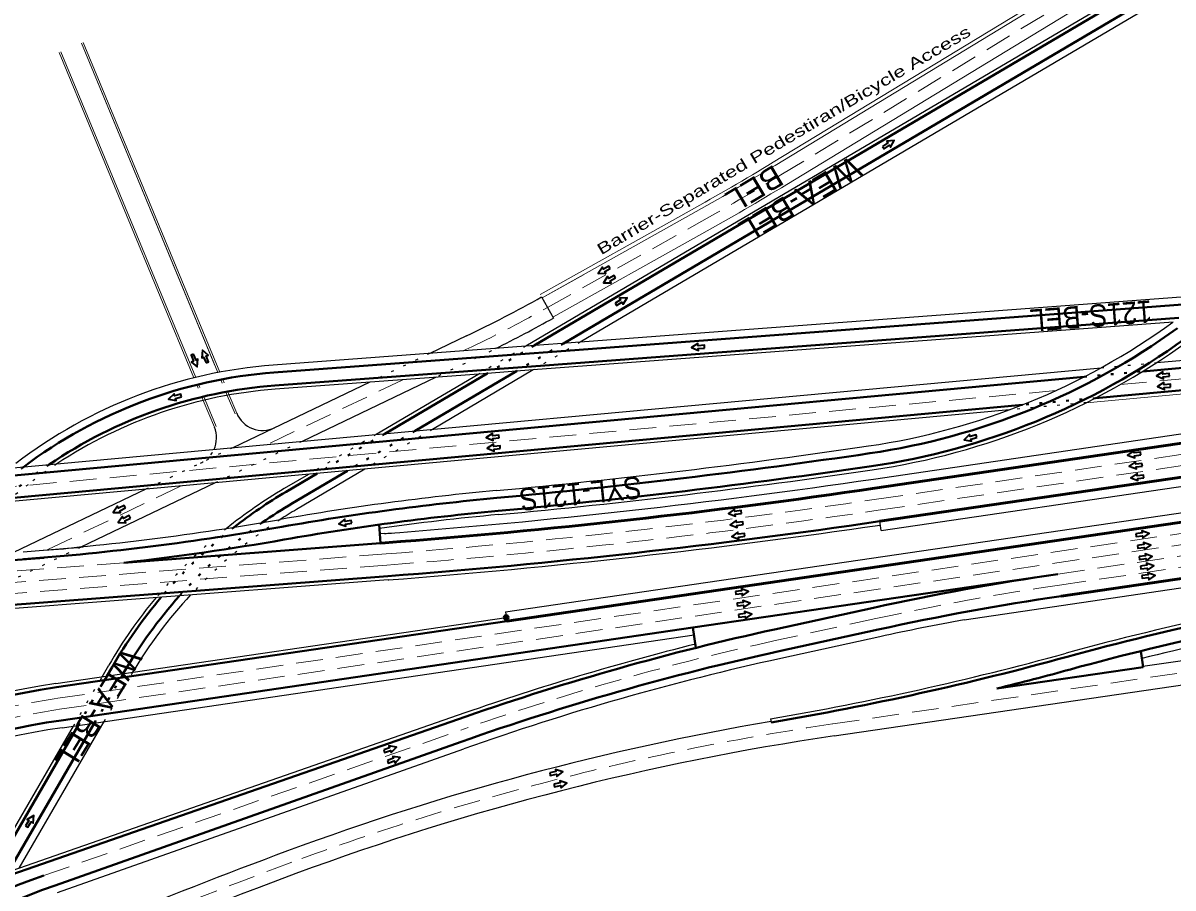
# Model space of a CAD drawing. Extents: x 2329387 to 2347382, y 6951580 to 6987999.
# Drawn here: x 2332942 to 2334179, y 6964414 to 6965345 of the extents above; entities that cross this region are included whole.
import ezdxf

# ---------------------------------------------------------------- set-up
doc = ezdxf.new("R2010")
doc.units = 0
doc.header["$LTSCALE"] = 9.6
doc.header["$PDMODE"] = 32
doc.header["$PDSIZE"] = 4.8
doc.linetypes.add('DOTTED', pattern=[1.5, 0.3, -1.2])
doc.linetypes.add('MEDIUM_DASHED', pattern=[4.5, 3, -1.5])
for name, color, linetype, lineweight in [('26', 7, 'Continuous', 53), ('27', 7, 'Continuous', 40), ('28', 7, 'Continuous', 25), ('3', 7, 'Continuous', 13), ('41', 7, 'Continuous', 35), ('50', 7, 'MEDIUM_DASHED', 13)]:
    doc.layers.add(name, color=color, linetype=linetype, lineweight=lineweight)
doc.layers.add('40', color=7, linetype='Continuous')

msp = doc.modelspace()

# ---------------------------------------------------------------- linework, layer by layer
at = {"layer": '26', "lineweight": 25}
for p, q in [((2333856.94, 6964854.018), (2334717.176, 6964980.367)), ((2333865.078, 6964798.612), (2334838.157, 6964941.536)), ((2333460.788, 6964710.931), (2334837.888, 6964913.196)), ((2333954.558, 6964702.596), (2334837.12, 6964832.225)), ((2333865.078, 6964798.612), (2333863.625, 6964808.506)), ((2333330.761, 6964795.33), (2333325.743, 6964794.947)), ((2333460.788, 6964710.931), (2333462.241, 6964701.037))]:
    msp.add_line(p, q, dxfattribs=at)
at = {"layer": '26'}
for p, q in [((2333858.393, 6964844.124), (2334718.629, 6964970.474)), ((2333863.625, 6964808.506), (2334838.253, 6964951.657)), ((2333462.241, 6964701.037), (2334837.792, 6964903.075)), ((2334058.85, 6964728.022), (2334837.216, 6964842.346)), ((2333331.527, 6964785.36), (2333326.499, 6964784.975))]:
    msp.add_line(p, q, dxfattribs=at)
at = {"layer": '26', "lineweight": 25}
for start, end in [(274.37265, 278.35573), (274.37261, 274.42831)]:
    msp.add_arc((2332749.984, 6972390.598), 7617.44, start, end, dxfattribs=at)
at = {"layer": '26'}
msp.add_arc((2332749.984, 6972390.598), 7627.44, 274.37267, 278.35573, dxfattribs=at)
at = {"layer": '27', "lineweight": 25}
for p, q in [((2334135.256, 6965381.515), (2333482.819, 6964996.963)), ((2334148.458, 6965359.116), (2333541.47, 6965001.352)), ((2334223.01, 6965052.354), (2333541.47, 6965001.352)), ((2334161.708, 6964979.364), (2334839.107, 6965041.79)), ((2334179.397, 6965023.018), (2333490.801, 6964971.488)), ((2333541.47, 6965001.352), (2333482.819, 6964996.963)), ((2333482.819, 6964996.963), (2333211.077, 6964976.628)), ((2332915.444, 6964864.514), (2334101.913, 6964973.853)), ((2333432.151, 6964967.099), (2333213.018, 6964950.701)), ((2333432.151, 6964967.099), (2333321.608, 6964901.944)), ((2333490.801, 6964971.488), (2333382.302, 6964907.537)), ((2333490.801, 6964971.488), (2333432.151, 6964967.099)), ((2334003.397, 6964928.622), (2332585.403, 6964797.946)), ((2333309.597, 6964864.685), (2333235.951, 6964821.277)), ((2333248.903, 6964859.091), (2333222.748, 6964843.675)), ((2333334.547, 6964745.474), (2333044.587, 6964723.303)), ((2333044.587, 6964723.303), (2332756.491, 6964701.275)), ((2332977.04, 6964633.814), (2333461.66, 6964704.994)), ((2332984.013, 6964586.324), (2333663.872, 6964686.18)), ((2333863.859, 6964684.262), (2333757.104, 6964660.877)), ((2333026.817, 6964641.126), (2333034.057, 6964653.615)), ((2333417.24, 6964602.202), (2332888.696, 6964418.182)), ((2332937.472, 6964435.164), (2333028.925, 6964592.92)), ((2333746.233, 6964595.957), (2333746.903, 6964592.013)), ((2332910.5, 6964440.478), (2332996.075, 6964588.095)), ((2332978.864, 6964409.03), (2333415.952, 6964563.598))]:
    msp.add_line(p, q, dxfattribs=at)
at = {"layer": '27'}
for p, q in [((2334137.287, 6965378.069), (2333491.842, 6964997.639)), ((2334144.396, 6965366.008), (2333523.423, 6965000.002)), ((2334208.79, 6965043.268), (2333525.879, 6964992.163)), ((2334185.648, 6965027.497), (2333498.596, 6964976.082)), ((2334146.832, 6964969.959), (2334839.031, 6965033.749)), ((2334838.802, 6965009.626), (2334095.849, 6964941.159)), ((2333525.879, 6964992.163), (2333467.229, 6964987.774)), ((2333467.229, 6964987.774), (2333211.674, 6964968.65)), ((2333498.596, 6964976.082), (2333439.946, 6964971.693)), ((2332916.178, 6964856.548), (2334083.684, 6964964.14)), ((2333439.946, 6964971.693), (2333212.719, 6964954.689)), ((2333441.174, 6964967.774), (2333330.945, 6964902.805)), ((2333472.755, 6964970.138), (2333363.627, 6964905.816)), ((2334017.13, 6964933.905), (2332585.036, 6964801.929)), ((2333258.241, 6964859.952), (2333224.78, 6964840.23)), ((2333290.922, 6964862.964), (2333231.888, 6964828.169)), ((2333324.987, 6964804.918), (2333326.499, 6964784.977)), ((2333326.499, 6964784.975), (2333050.228, 6964763.851)), ((2332964.682, 6964769.345), (2332752.526, 6964753.123)), ((2333334.226, 6964749.461), (2332756.186, 6964705.263)), ((2333662.709, 6964694.095), (2334055.362, 6964751.767)), ((2333857.012, 6964715.521), (2333750.267, 6964692.138)), ((2332977.621, 6964629.857), (2333462.241, 6964701.037)), ((2332982.86, 6964594.24), (2333662.709, 6964694.095)), ((2333665.906, 6964672.328), (2333662.709, 6964694.095)), ((2333862.147, 6964692.077), (2333755.392, 6964668.692)), ((2334144.509, 6964668.841), (2334147.052, 6964651.527)), ((2333031.871, 6964641.868), (2333037.518, 6964651.609)), ((2333989.579, 6964628.398), (2334147.052, 6964651.527)), ((2333418.555, 6964598.424), (2332890.012, 6964414.405)), ((2332913.96, 6964438.472), (2333001.129, 6964588.838)), ((2332926.067, 6964431.442), (2333018.817, 6964591.436)), ((2332976.196, 6964416.572), (2333413.284, 6964571.14))]:
    msp.add_line(p, q, dxfattribs=at)
at = {"layer": '27', "linetype": 'DOTTED', "lineweight": 25}
for p, q in [((2333541.47, 6965001.352), (2333490.801, 6964971.488)), ((2333482.819, 6964996.963), (2333432.151, 6964967.099)), ((2334101.913, 6964973.853), (2334161.708, 6964979.364)), ((2334086.159, 6964936.249), (2334003.397, 6964928.622)), ((2333321.608, 6964901.944), (2333248.903, 6964859.091)), ((2333382.302, 6964907.537), (2333309.597, 6964864.685)), ((2332922.383, 6964829.001), (2332949.872, 6964850.133)), ((2332996.075, 6964588.095), (2333026.817, 6964641.126)), ((2333028.925, 6964592.92), (2333056.551, 6964640.576))]:
    msp.add_line(p, q, dxfattribs=at)
at = {"layer": '27', "linetype": 'DOTTED'}
for p, q in [((2333491.842, 6964997.639), (2333441.174, 6964967.774)), ((2333523.423, 6965000.002), (2333472.755, 6964970.138)), ((2334083.684, 6964964.14), (2334146.832, 6964969.959)), ((2334095.849, 6964941.159), (2334017.13, 6964933.905)), ((2333330.945, 6964902.805), (2333258.241, 6964859.952)), ((2333363.627, 6964905.816), (2333290.922, 6964862.964)), ((2332914.926, 6964828.314), (2332947.433, 6964853.303)), ((2333001.129, 6964588.838), (2333031.871, 6964641.868))]:
    msp.add_line(p, q, dxfattribs=at)
at = {"layer": '27', "lineweight": 13}
msp.add_line((2334715.143, 6964994.213), (2334086.159, 6964936.249), dxfattribs=at)
at = {"layer": '27', "linetype": 'DOTTED'}
msp.add_lwpolyline([(2333018.817, 6964591.436), (2333049.559, 6964644.466), (2333049.63, 6964644.588)], dxfattribs=at)
at = {"layer": '27'}
for centre, radius, start, end in [((2339406.145, 6959556.474), 7976, 170.51466, 170.51466), ((2333743.882, 6965623.759), 750, 278.35573, 305.92709), ((2333743.882, 6965623.759), 764, 278.35573, 305.92709), ((2333249.733, 6964460.072), 510, 94.27965, 127.07243), ((2333249.733, 6964460.072), 496, 94.27965, 124.36037), ((2332749.984, 6972390.598), 7589.44, 275.30492, 278.35573), ((2332749.984, 6972390.598), 7603.44, 275.30492, 278.35573), ((2333490.852, 6964388.808), 524, 120.51546, 127.92482), ((2333490.852, 6964388.808), 510, 120.51546, 124.89956), ((2333716.541, 6961981.147), 2864.789, 95.30492, 99.97649), ((2333716.541, 6961981.147), 2850.789, 95.30492, 99.97649), ((2332723.925, 6967624.087), 2864.789, 274.37245, 279.97649), ((2332749.984, 6972390.598), 7663.44, 274.37234, 278.35573), ((2332723.925, 6967624.087), 2878.789, 276.50831, 279.97649), ((2334475.157, 6961893.643), 2888.789, 98.35573, 102.35573), ((2333490.852, 6964388.808), 510, 138.26212, 149.89874), ((2334475.157, 6961893.643), 2864.789, 98.35573, 102.35573), ((2334828.642, 6961886.94), 2878.789, 98.35573, 105.37884), ((2333490.852, 6964388.808), 524, 139.83129, 149.89874), ((2334828.642, 6961886.94), 2864.789, 98.35573, 105.37884), ((2334368.402, 6961870.258), 2888.789, 102.35552, 109.19624), ((2334368.402, 6961870.258), 2864.789, 102.35573, 109.47521), ((2333200.623, 6967805.962), 3260.044, 279.64646, 285.37884), ((2333200.623, 6967805.962), 3274.044, 283.94397, 285.37884), ((2333105.715, 6963757.74), 881.473, 98.35573, 134.73223), ((2333105.715, 6963757.74), 845.473, 98.35522, 132.84387), ((2333243.898, 6963625.567), 849, 109.23607, 171.39072), ((2333254.585, 6963629.346), 835, 109.47521, 171.39072)]:
    msp.add_arc(centre, radius, start, end, dxfattribs=at)
at = {"layer": '27', "lineweight": 25}
for centre, radius, start, end in [((2333743.882, 6965623.759), 742, 278.35573, 305.92709), ((2333743.882, 6965623.759), 768, 278.35573, 305.92709), ((2333249.733, 6964460.072), 518, 94.27965, 127.55163), ((2333249.733, 6964460.072), 492, 94.27965, 123.51197), ((2332749.984, 6972390.598), 7581.44, 275.30492, 278.35573), ((2332749.984, 6972390.598), 7607.44, 275.30492, 278.35573), ((2333490.852, 6964388.808), 528, 120.51546, 128.697), ((2333716.541, 6961981.147), 2872.789, 95.30492, 99.97649), ((2333490.852, 6964388.808), 502, 120.51546, 122.87637), ((2333716.541, 6961981.147), 2846.789, 95.30492, 97.89949), ((2332723.925, 6967624.087), 2856.789, 274.37245, 279.97649), ((2332749.984, 6972390.598), 7667.44, 274.37245, 278.35573), ((2332746.271, 6967625.796), 2856.789, 274.37245, 275.22848), ((2332749.984, 6972390.598), 7667.44, 274.37245, 274.37956), ((2333490.852, 6964388.808), 502, 137.30458, 149.18609), ((2334828.642, 6961886.94), 2882.789, 98.35573, 105.37884), ((2333490.852, 6964388.808), 528, 140.2569, 149.89874), ((2334828.642, 6961886.94), 2856.789, 98.35573, 103.83151), ((2334475.157, 6961893.643), 2856.789, 100.4998, 102.35573), ((2334368.402, 6961870.258), 2892.789, 104.06637, 109.19624), ((2333200.623, 6967805.962), 3256.044, 279.64646, 285.37884), ((2334368.402, 6961870.258), 2856.789, 102.35573, 109.47521), ((2333105.715, 6963757.74), 885.473, 98.35573, 134.91734), ((2333105.715, 6963757.74), 837.473, 98.35584, 132.36198)]:
    msp.add_arc(centre, radius, start, end, dxfattribs=at)
at = {"layer": '27', "linetype": 'DOTTED'}
for centre, radius, start, end in [((2333249.733, 6964460.072), 510, 127.07243, 127.55151), ((2333249.733, 6964460.072), 496, 124.36037, 127.55163), ((2333490.852, 6964388.808), 510, 124.89956, 138.26212), ((2333490.852, 6964388.808), 524, 127.92482, 139.83129)]:
    msp.add_arc(centre, radius, start, end, dxfattribs=at)
at = {"layer": '27', "linetype": 'DOTTED', "lineweight": 25}
for centre, radius, start, end in [((2333249.733, 6964460.072), 492, 123.51197, 127.55149), ((2333490.852, 6964388.808), 502, 122.87637, 137.30458), ((2333490.852, 6964388.808), 528, 128.697, 140.25691), ((2333490.852, 6964388.808), 502, 149.18609, 149.89874)]:
    msp.add_arc(centre, radius, start, end, dxfattribs=at)
at = {"layer": '27'}
msp.add_point((2333461.66, 6964704.994), dxfattribs=at)
at = {"layer": '28'}
for p, q in [((2333499.851, 6965050.075), (2333512.543, 6965027.383)), ((2333419.138, 6965008.238), (2333379.42, 6964989.226)), ((2333386.236, 6964963.663), (2333241.972, 6964894.605)), ((2333314.861, 6964958.322), (2333167.398, 6964887.733)), ((2333073.868, 6964842.961), (2332931.551, 6964774.835)), ((2333148.442, 6964849.833), (2333003.913, 6964780.649)), ((2334146.907, 6964652.517), (2334832.144, 6964753.163)), ((2333814.811, 6964577.46), (2334191.855, 6964632.839))]:
    msp.add_line(p, q, dxfattribs=at)
at = {"layer": '28', "linetype": 'DOTTED'}
for p, q in [((2333379.42, 6964989.226), (2333314.861, 6964958.322)), ((2333430.364, 6964984.786), (2333386.236, 6964963.663)), ((2333241.972, 6964894.605), (2333148.442, 6964849.833)), ((2333167.398, 6964887.733), (2333073.868, 6964842.961)), ((2333003.913, 6964780.649), (2332853.61, 6964708.7))]:
    msp.add_line(p, q, dxfattribs=at)
at = {"layer": '28'}
for centre, radius, start, end in [((2332801.108, 6966299.334), 1431.395, 295.57979, 299.21942), ((2332801.108, 6966299.334), 1457.395, 296.4533, 299.21942), ((2334230.973, 6961744.07), 2889.789, 99.64647, 110.34212), ((2334230.973, 6961744.07), 2863.789, 98.35573, 110.34212), ((2335226.842, 6959057.955), 5754.57, 110.34212, 114.63914), ((2335226.842, 6959057.955), 5728.57, 110.34212, 117.07917)]:
    msp.add_arc(centre, radius, start, end, dxfattribs=at)
at = {"layer": '28', "linetype": 'DOTTED'}
for centre, radius, start, end in [((2332801.108, 6966299.334), 1457.395, 295.57979, 296.4533), ((2333119.96, 6964898.285), 30, 295.57996, 335.57184)]:
    msp.add_arc(centre, radius, start, end, dxfattribs=at)
at = {"layer": '3'}
for p, q in [((2333151.428, 6964968.659), (2333004.575, 6965323.26)), ((2333148.328, 6964976.146), (2333004.575, 6965323.26)), ((2333153.434, 6964969.042), (2333006.423, 6965324.025)), ((2333125.636, 6964962.988), (2332980.553, 6965313.312)), ((2333127.601, 6964963.469), (2332982.401, 6965314.077)), ((2333147.678, 6964909.764), (2333135.704, 6964938.676)), ((2333149.525, 6964910.529), (2333137.676, 6964939.141)), ((2333169.885, 6964924.092), (2333161.594, 6964944.113)), ((2333171.733, 6964924.857), (2333163.608, 6964944.476))]:
    msp.add_line(p, q, dxfattribs=at)
at = {"layer": '3', "linetype": 'DOTTED'}
for p, q in [((2333137.676, 6964939.141), (2333127.601, 6964963.469)), ((2333161.594, 6964944.113), (2333151.428, 6964968.659)), ((2333163.608, 6964944.476), (2333153.434, 6964969.042)), ((2333135.704, 6964938.676), (2333125.636, 6964962.988))]:
    msp.add_line(p, q, dxfattribs=at)
at = {"layer": '3', "lineweight": 25}
for centre, start, end in [((2333199.45, 6964936.336), 202.49623, 295.57996), ((2333119.96, 6964898.285), 335.57184, 22.49623)]:
    msp.add_arc(centre, 30, start, end, dxfattribs=at)
at = {"layer": '41'}
for points in [[(2333866.718, 6965212.132), (2333868.353, 6965209.615), (2333874.061, 6965213.323), (2333875.389, 6965211.279), (2333879.368, 6965218.37), (2333871.272, 6965217.617), (2333872.426, 6965215.839)], [(2333573.756, 6965080.674), (2333572.306, 6965083.301), (2333566.347, 6965080.012), (2333565.169, 6965082.146), (2333560.691, 6965075.358), (2333568.821, 6965075.529), (2333567.797, 6965077.385)], [(2333579.448, 6965070.536), (2333577.998, 6965073.163), (2333572.039, 6965069.874), (2333570.861, 6965072.008), (2333566.383, 6965065.22), (2333574.513, 6965065.391), (2333573.489, 6965067.247)], [(2333578.842, 6965043.531), (2333580.345, 6965040.934), (2333586.236, 6965044.344), (2333587.457, 6965042.234), (2333591.795, 6965049.112), (2333583.671, 6965048.775), (2333584.733, 6965046.941)], [(2333125.284, 6964988.398), (2333122.513, 6964987.246), (2333125.126, 6964980.96), (2333122.875, 6964980.025), (2333129.129, 6964974.827), (2333129.854, 6964982.926), (2333127.897, 6964982.112)], [(2333138.72, 6964979.07), (2333141.491, 6964980.222), (2333138.878, 6964986.507), (2333141.128, 6964987.443), (2333134.875, 6964992.641), (2333134.15, 6964984.542), (2333136.107, 6964985.355)], [(2333675.191, 6964994.985), (2333674.973, 6964997.978), (2333668.184, 6964997.482), (2333668.006, 6964999.912), (2333661.101, 6964995.619), (2333668.557, 6964992.375), (2333668.403, 6964994.489)], [(2334175.471, 6964964.629), (2334175.215, 6964967.619), (2334168.433, 6964967.039), (2334168.225, 6964969.467), (2334161.374, 6964965.088), (2334168.87, 6964961.937), (2334168.689, 6964964.049)], [(2334176.642, 6964953.033), (2334176.386, 6964956.023), (2334169.604, 6964955.443), (2334169.396, 6964957.871), (2334162.544, 6964953.492), (2334170.041, 6964950.341), (2334169.86, 6964952.453)], [(2333112.316, 6964942.537), (2333111.445, 6964945.409), (2333104.931, 6964943.433), (2333104.223, 6964945.766), (2333098.43, 6964940.059), (2333106.417, 6964938.533), (2333105.802, 6964940.562)], [(2333454.206, 6964898.343), (2333453.929, 6964901.331), (2333447.151, 6964900.704), (2333446.926, 6964903.13), (2333440.105, 6964898.704), (2333447.623, 6964895.605), (2333447.428, 6964897.716)], [(2333968.23, 6964898.893), (2333967.335, 6964901.757), (2333960.838, 6964899.728), (2333960.112, 6964902.054), (2333954.366, 6964896.301), (2333962.365, 6964894.84), (2333961.733, 6964896.863)], [(2333455.362, 6964886.774), (2333455.085, 6964889.762), (2333448.308, 6964889.135), (2333448.083, 6964891.562), (2333441.262, 6964887.135), (2333448.78, 6964884.036), (2333448.584, 6964886.147)], [(2334144.525, 6964879.994), (2334144.137, 6964882.969), (2334137.388, 6964882.089), (2334137.072, 6964884.506), (2334130.421, 6964879.827), (2334138.05, 6964877.011), (2334137.776, 6964879.113)], [(2334146.279, 6964867.901), (2334145.891, 6964870.876), (2334139.141, 6964869.996), (2334138.826, 6964872.412), (2334132.175, 6964867.734), (2334139.804, 6964864.918), (2334139.53, 6964867.02)], [(2334147.996, 6964855.332), (2334147.608, 6964858.307), (2334140.859, 6964857.426), (2334140.543, 6964859.843), (2334133.893, 6964855.165), (2334141.521, 6964852.349), (2334141.247, 6964854.451)], [(2333051.88, 6964822.962), (2333050.521, 6964825.637), (2333044.452, 6964822.556), (2333043.349, 6964824.729), (2333038.639, 6964818.1), (2333046.77, 6964817.99), (2333045.811, 6964819.88)], [(2333057.371, 6964812.033), (2333056.013, 6964814.709), (2333049.944, 6964811.627), (2333048.84, 6964813.8), (2333044.131, 6964807.171), (2333052.262, 6964807.062), (2333051.302, 6964808.952)], [(2333715.01, 6964817.11), (2333714.622, 6964820.085), (2333707.872, 6964819.205), (2333707.557, 6964821.622), (2333700.906, 6964816.943), (2333708.535, 6964814.128), (2333708.261, 6964816.229)], [(2333295.526, 6964806.619), (2333295.004, 6964809.573), (2333288.301, 6964808.388), (2333287.876, 6964810.788), (2333281.444, 6964805.813), (2333289.193, 6964803.346), (2333288.824, 6964805.433)], [(2333716.764, 6964805.017), (2333716.376, 6964807.992), (2333709.626, 6964807.112), (2333709.311, 6964809.528), (2333702.66, 6964804.85), (2333710.289, 6964802.034), (2333710.014, 6964804.136)], [(2333718.481, 6964792.448), (2333718.093, 6964795.423), (2333711.344, 6964794.543), (2333711.028, 6964796.959), (2333704.377, 6964792.281), (2333712.006, 6964789.465), (2333711.732, 6964791.567)], [(2334139.405, 6964795.133), (2334139.793, 6964792.158), (2334146.542, 6964793.038), (2334146.858, 6964790.621), (2334153.509, 6964795.3), (2334145.88, 6964798.116), (2334146.154, 6964796.014)], [(2334141.122, 6964782.564), (2334141.51, 6964779.589), (2334148.26, 6964780.469), (2334148.575, 6964778.052), (2334155.226, 6964782.731), (2334147.597, 6964785.546), (2334147.872, 6964783.445)], [(2334142.876, 6964770.471), (2334143.264, 6964767.496), (2334150.014, 6964768.376), (2334150.329, 6964765.959), (2334156.98, 6964770.638), (2334149.351, 6964773.453), (2334149.625, 6964771.352)], [(2334144.36, 6964760.329), (2334144.748, 6964757.353), (2334151.498, 6964758.234), (2334151.813, 6964755.817), (2334158.464, 6964760.495), (2334150.836, 6964763.311), (2334151.11, 6964761.209)], [(2334145.845, 6964750.187), (2334146.233, 6964747.211), (2334152.982, 6964748.092), (2334153.298, 6964745.675), (2334159.948, 6964750.353), (2334152.32, 6964753.169), (2334152.594, 6964751.067)], [(2333708.327, 6964732.929), (2333708.715, 6964729.954), (2333715.465, 6964730.834), (2333715.78, 6964728.417), (2333722.431, 6964733.096), (2333714.803, 6964735.911), (2333715.077, 6964733.81)], [(2333710.045, 6964720.36), (2333710.433, 6964717.384), (2333717.182, 6964718.265), (2333717.498, 6964715.848), (2333724.148, 6964720.527), (2333716.52, 6964723.342), (2333716.794, 6964721.241)], [(2333711.799, 6964708.267), (2333712.187, 6964705.291), (2333718.936, 6964706.172), (2333719.252, 6964703.755), (2333725.902, 6964708.433), (2333718.274, 6964711.249), (2333718.548, 6964709.147)], [(2333329.844, 6964562.429), (2333330.842, 6964559.6), (2333337.261, 6964561.865), (2333338.072, 6964559.567), (2333343.604, 6964565.527), (2333335.557, 6964566.694), (2333336.262, 6964564.695)], [(2333333.847, 6964551.089), (2333334.846, 6964548.259), (2333341.264, 6964550.524), (2333342.075, 6964548.226), (2333347.607, 6964554.186), (2333339.56, 6964555.353), (2333340.265, 6964553.354)], [(2333508.572, 6964537.913), (2333509.147, 6964534.968), (2333515.828, 6964536.273), (2333516.295, 6964533.881), (2333522.637, 6964538.97), (2333514.846, 6964541.298), (2333515.252, 6964539.218)], [(2333513.059, 6964525.57), (2333513.634, 6964522.625), (2333520.314, 6964523.93), (2333520.782, 6964521.538), (2333527.124, 6964526.628), (2333519.333, 6964528.956), (2333519.739, 6964526.875)], [(2332944.496, 6964480.646), (2332947.054, 6964479.076), (2332950.614, 6964484.878), (2332952.691, 6964483.603), (2332953.236, 6964491.717), (2332946.25, 6964487.556), (2332948.056, 6964486.447)]]:
    msp.add_lwpolyline(points, close=True, dxfattribs=at)
at = {"layer": '50', "linetype": 'Continuous'}
for p, q in [((2333748.995, 6965195.06), (2334112.926, 6965416.476)), ((2333751.074, 6965191.643), (2334115.005, 6965413.059)), ((2333763.549, 6965171.14), (2334127.48, 6965392.556)), ((2333498.387, 6965052.693), (2333658.572, 6965142.289)), ((2333500.339, 6965049.202), (2333660.525, 6965138.798)), ((2333512.055, 6965028.256), (2333672.241, 6965117.852)), ((2333544.727, 6965074.03), (2333500.339, 6965049.202))]:
    msp.add_line(p, q, dxfattribs=at)
at = {"layer": '50'}
for p, q in [((2333757.312, 6965181.391), (2334121.243, 6965402.807)), ((2333506.197, 6965038.729), (2333666.383, 6965128.325)), ((2334838.917, 6965021.687), (2334122.695, 6964955.684)), ((2333424.751, 6964996.512), (2333415.108, 6964991.896)), ((2333860.137, 6964832.251), (2334838.483, 6964975.949)), ((2333861.881, 6964820.379), (2334838.368, 6964963.803)), ((2333350.549, 6964960.992), (2333204.685, 6964891.169)), ((2334053.126, 6964949.273), (2332583.934, 6964813.879)), ((2332979.358, 6964617.983), (2334837.677, 6964890.929)), ((2332981.102, 6964606.111), (2334837.562, 6964878.783)), ((2334057.106, 6964739.894), (2334837.331, 6964854.492)), ((2333111.155, 6964846.397), (2332967.679, 6964777.717)), ((2334055.362, 6964751.767), (2334448.416, 6964809.498)), ((2333332.433, 6964773.394), (2332754.356, 6964729.193)), ((2333050.228, 6964763.851), (2332753.441, 6964741.158)), ((2333333.348, 6964761.429), (2332755.271, 6964717.228)), ((2333813.025, 6964590.337), (2334821.609, 6964738.476)), ((2333859.58, 6964703.799), (2333752.833, 6964680.416)), ((2332964.186, 6964427.166), (2333420.612, 6964586.433))]:
    msp.add_line(p, q, dxfattribs=at)
at = {"layer": '50', "linetype": 'Continuous'}
for radius in [2860.789, 2864.789, 2888.789]:
    msp.add_arc((2332262.062, 6967639.062), radius, 299.21942, 301.31637, dxfattribs=at)
at = {"layer": '50'}
for centre, radius, start, end in [((2332262.062, 6967639.062), 2876.789, 299.21942, 301.31637), ((2332801.108, 6966299.334), 1444.395, 295.57979, 299.21942), ((2332749.984, 6972390.598), 7639.44, 274.37261, 278.35573), ((2332749.984, 6972390.598), 7651.44, 274.37261, 278.35573), ((2334475.157, 6961893.643), 2876.789, 98.35573, 102.35573), ((2334368.402, 6961870.258), 2876.789, 102.35557, 109.23607), ((2333105.715, 6963757.74), 869.473, 98.3562, 134.14917), ((2333105.715, 6963757.74), 857.473, 98.35615, 133.5213), ((2334230.973, 6961744.07), 2876.789, 98.35573, 110.34212), ((2335226.842, 6959057.955), 5741.57, 110.34212, 116.7593)]:
    msp.add_arc(centre, radius, start, end, dxfattribs=at)

# ---------------------------------------------------------------- texts
at = {"layer": '40'}
for rotation, p in [(210.882, (2333833.768, 6965202.678)), (238.362, (2333050.389, 6964673.958))]:
    msp.add_text('WEA-BEL', height=24, rotation=rotation, dxfattribs=at).set_placement(p)
for s, rotation, width, p in [('BEL', 210.882, 1.05, (2333750.085, 6965193.226)), ('121S-BEL', 184.428, 0.9, (2334155.729, 6965046.551)), ('SYL-121S', 185.984, 0.9, (2333605.927, 6964857.238))]:
    msp.add_text(s, height=24, rotation=rotation, dxfattribs=dict(at, width=width)).set_placement(p)
at = {"layer": '50', "width": 1.45}
msp.add_text('Barrier-Separated Pedestiran/Bicycle Access', height=12, rotation=30.759, dxfattribs=at).set_placement((2333563.947, 6965094.877))

doc.saveas('drawing.dxf')
